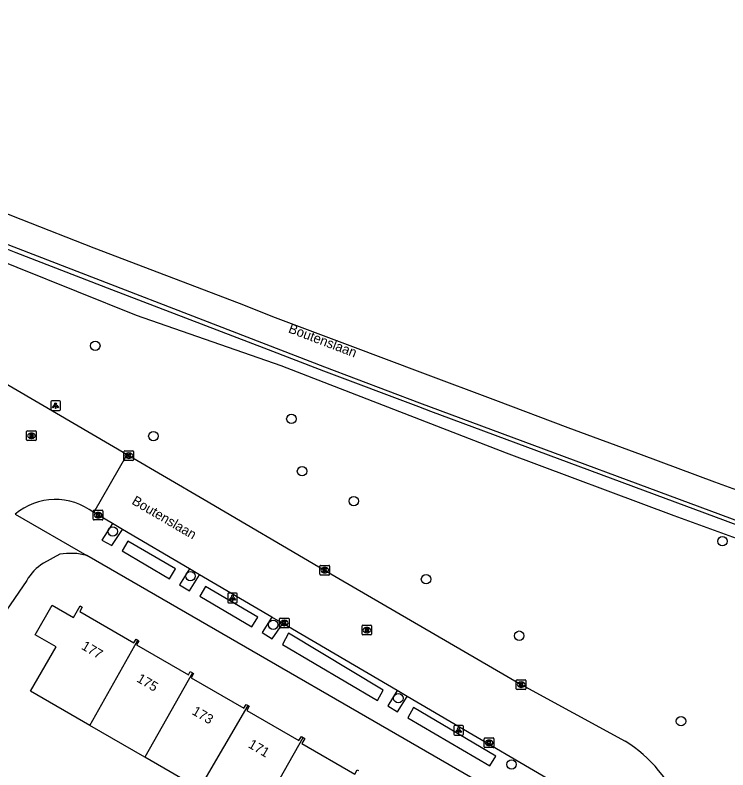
# Model space of a CAD drawing. Extents: x 160158 to 160921, y 381517 to 382041.
# Drawn here: x 160717.9 to 160791.9, y 381808.9 to 381887.3 of the extents above; entities that cross this region are included whole.
import ezdxf

# ---------------------------------------------------------------- set-up
doc = ezdxf.new("R2010")
doc.units = 0
for name, color, linetype in [('IMGEO_Boom', 7, 'Continuous'), ('IMGEO_Haag', 7, 'Continuous'), ('IMGEO_Kolk', 7, 'Continuous'), ('IMGEO_Lichtpunt', 7, 'Continuous'), ('IMGEO_Openbare_ruimte_label', 7, 'Continuous'), ('IMGEO_Pand', 7, 'Continuous'), ('IMGEO_Pand_nummerreeks', 7, 'Continuous'), ('IMGEO_Rijbaan_lokaal_open', 7, 'Continuous'), ('IMGEO_Rijbaan_regionaal_gesloten', 7, 'Continuous'), ('IMGEO_Rioolput', 7, 'Continuous'), ('IMGEO_Voetpad_open', 7, 'Continuous')]:
    doc.layers.add(name, color=color, linetype=linetype)

msp = doc.modelspace()

# ---------------------------------------------------------------- linework, layer by layer
at = {"layer": 'IMGEO_Boom'}
for centre in [(160726.203, 381852.954), (160746.556, 381845.36), (160732.229, 381843.573), (160747.662, 381839.926), (160753.032, 381836.818), (160728.01, 381833.663), (160791.302, 381832.657), (160736.072, 381829.024), (160760.535, 381828.709), (160744.672, 381823.974), (160770.206, 381822.841), (160757.66, 381816.345), (160787.002, 381813.963), (160769.415, 381809.472)]:
    msp.add_circle(centre, 0.489, dxfattribs=at)
at = {"layer": 'IMGEO_Haag'}
msp.add_lwpolyline([(160745.511, 381850.872), (160730.476, 381856.085), (160711.881, 381863.555), (160711.475, 381863.718), (160712.09, 381864.933), (160713.245, 381864.496), (160717.081, 381862.972), (160717.946, 381862.628), (160727.896, 381858.807), (160743.715, 381852.731), (160749.887, 381850.361), (160759.752, 381846.628), (160760.992, 381846.167), (160784.208, 381837.543), (160791.578, 381834.806), (160797.451, 381832.626), (160796.951, 381831.418), (160786.29, 381835.29), (160768.888, 381841.8), (160745.511, 381850.872)], dxfattribs=at)
at = {"layer": 'IMGEO_Kolk'}
for p, q in [((160729.183, 381841.112), (160729.183, 381841.964)), ((160729.258, 381842.038), (160730.11, 381842.038)), ((160729.671, 381841.818), (160729.696, 381841.818)), ((160730.184, 381841.964), (160730.184, 381841.112)), ((160730.11, 381841.038), (160729.258, 381841.038)), ((160729.694, 381841.258), (160729.669, 381841.258)), ((160725.997, 381834.935), (160725.997, 381835.787)), ((160726.072, 381835.861), (160726.924, 381835.861)), ((160726.485, 381835.641), (160726.51, 381835.641)), ((160726.998, 381835.787), (160726.998, 381834.935)), ((160726.924, 381834.861), (160726.072, 381834.861)), ((160726.508, 381835.081), (160726.483, 381835.081)), ((160749.521, 381829.216), (160749.521, 381830.068)), ((160749.596, 381830.142), (160750.448, 381830.142)), ((160750.009, 381829.922), (160750.034, 381829.922)), ((160750.522, 381830.068), (160750.522, 381829.216)), ((160750.448, 381829.142), (160749.596, 381829.142)), ((160750.032, 381829.362), (160750.007, 381829.362)), ((160745.316, 381823.737), (160745.316, 381824.589)), ((160745.391, 381824.663), (160746.243, 381824.663)), ((160745.804, 381824.443), (160745.829, 381824.443)), ((160746.317, 381824.589), (160746.317, 381823.737)), ((160746.243, 381823.663), (160745.391, 381823.663)), ((160745.827, 381823.883), (160745.802, 381823.883)), ((160769.907, 381817.333), (160769.907, 381818.185)), ((160769.982, 381818.259), (160770.834, 381818.259)), ((160770.395, 381818.039), (160770.42, 381818.039)), ((160770.908, 381818.185), (160770.908, 381817.333)), ((160770.834, 381817.259), (160769.982, 381817.259)), ((160770.418, 381817.479), (160770.393, 381817.479)), ((160766.579, 381811.296), (160766.579, 381812.148)), ((160766.654, 381812.222), (160767.506, 381812.222)), ((160767.067, 381812.002), (160767.092, 381812.002)), ((160767.58, 381812.148), (160767.58, 381811.296)), ((160767.506, 381811.222), (160766.654, 381811.222)), ((160767.09, 381811.442), (160767.065, 381811.442))]:
    msp.add_line(p, q, dxfattribs=at)
for points in [[(160729.183, 381841.112), (160729.183, 381841.964)], [(160729.258, 381842.038), (160730.11, 381842.038)], [(160729.504, 381841.738), (160729.627, 381841.738), (160729.627, 381841.587), (160729.757, 381841.738), (160729.921, 381841.738), (160729.775, 381841.587), (160729.928, 381841.338), (160729.776, 381841.338), (160729.691, 381841.502), (160729.627, 381841.435), (160729.627, 381841.338), (160729.504, 381841.338), (160729.504, 381841.738)], [(160730.184, 381841.964), (160730.184, 381841.112)], [(160730.11, 381841.038), (160729.258, 381841.038)], [(160725.997, 381834.935), (160725.997, 381835.787)], [(160726.072, 381835.861), (160726.924, 381835.861)], [(160726.318, 381835.561), (160726.441, 381835.561), (160726.441, 381835.41), (160726.571, 381835.561), (160726.735, 381835.561), (160726.589, 381835.41), (160726.742, 381835.161), (160726.59, 381835.161), (160726.505, 381835.325), (160726.441, 381835.258), (160726.441, 381835.161), (160726.318, 381835.161), (160726.318, 381835.561)], [(160726.998, 381835.787), (160726.998, 381834.935)], [(160726.924, 381834.861), (160726.072, 381834.861)], [(160749.521, 381829.216), (160749.521, 381830.068)], [(160749.596, 381830.142), (160750.448, 381830.142)], [(160749.842, 381829.842), (160749.965, 381829.842), (160749.965, 381829.691), (160750.095, 381829.842), (160750.259, 381829.842), (160750.113, 381829.691), (160750.266, 381829.442), (160750.114, 381829.442), (160750.029, 381829.606), (160749.965, 381829.539), (160749.965, 381829.442), (160749.842, 381829.442), (160749.842, 381829.842)], [(160750.522, 381830.068), (160750.522, 381829.216)], [(160750.448, 381829.142), (160749.596, 381829.142)], [(160745.316, 381823.737), (160745.316, 381824.589)], [(160745.391, 381824.663), (160746.243, 381824.663)], [(160745.637, 381824.363), (160745.76, 381824.363), (160745.76, 381824.212), (160745.89, 381824.363), (160746.054, 381824.363), (160745.908, 381824.212), (160746.061, 381823.963), (160745.909, 381823.963), (160745.824, 381824.127), (160745.76, 381824.06), (160745.76, 381823.963), (160745.637, 381823.963), (160745.637, 381824.363)], [(160746.317, 381824.589), (160746.317, 381823.737)], [(160746.243, 381823.663), (160745.391, 381823.663)], [(160769.907, 381817.333), (160769.907, 381818.185)], [(160769.982, 381818.259), (160770.834, 381818.259)], [(160770.908, 381818.185), (160770.908, 381817.333)], [(160770.834, 381817.259), (160769.982, 381817.259)], [(160770.228, 381817.959), (160770.351, 381817.959), (160770.351, 381817.808), (160770.481, 381817.959), (160770.645, 381817.959), (160770.499, 381817.808), (160770.652, 381817.559), (160770.5, 381817.559), (160770.415, 381817.723), (160770.351, 381817.656), (160770.351, 381817.559), (160770.228, 381817.559), (160770.228, 381817.959)], [(160766.579, 381811.296), (160766.579, 381812.148)], [(160766.654, 381812.222), (160767.506, 381812.222)], [(160766.9, 381811.922), (160767.023, 381811.922), (160767.023, 381811.771), (160767.153, 381811.922), (160767.317, 381811.922), (160767.171, 381811.771), (160767.324, 381811.522), (160767.172, 381811.522), (160767.087, 381811.686), (160767.023, 381811.619), (160767.023, 381811.522), (160766.9, 381811.522), (160766.9, 381811.922)], [(160767.58, 381812.148), (160767.58, 381811.296)], [(160767.506, 381811.222), (160766.654, 381811.222)]]:
    msp.add_lwpolyline(points, dxfattribs=at)
for centre, start, end in [((160729.26, 381841.962), 91.55205, 178.44795), ((160729.26, 381841.962), 91.55205, 178.44795), ((160730.108, 381841.962), 1.55205, 88.44795), ((160730.108, 381841.962), 1.55205, 88.44795), ((160729.26, 381841.114), 181.55205, 268.44795), ((160729.26, 381841.114), 181.55205, 268.44795), ((160730.108, 381841.114), 271.55205, 358.44795), ((160730.108, 381841.114), 271.55205, 358.44795), ((160726.074, 381835.785), 91.55205, 178.44795), ((160726.074, 381835.785), 91.55205, 178.44795), ((160726.922, 381835.785), 1.55205, 88.44795), ((160726.922, 381835.785), 1.55205, 88.44795), ((160726.074, 381834.937), 181.55205, 268.44795), ((160726.074, 381834.937), 181.55205, 268.44795), ((160726.922, 381834.937), 271.55205, 358.44795), ((160726.922, 381834.937), 271.55205, 358.44795), ((160749.598, 381830.066), 91.55205, 178.44795), ((160749.598, 381830.066), 91.55205, 178.44795), ((160750.446, 381830.066), 1.55205, 88.44795), ((160750.446, 381830.066), 1.55205, 88.44795), ((160749.598, 381829.218), 181.55205, 268.44795), ((160749.598, 381829.218), 181.55205, 268.44795), ((160750.446, 381829.218), 271.55205, 358.44795), ((160750.446, 381829.218), 271.55205, 358.44795), ((160745.393, 381824.587), 91.55205, 178.44795), ((160745.393, 381824.587), 91.55205, 178.44795), ((160746.241, 381824.587), 1.55205, 88.44795), ((160746.241, 381824.587), 1.55205, 88.44795), ((160745.393, 381823.739), 181.55205, 268.44795), ((160745.393, 381823.739), 181.55205, 268.44795), ((160746.241, 381823.739), 271.55205, 358.44795), ((160746.241, 381823.739), 271.55205, 358.44795), ((160769.984, 381818.183), 91.55205, 178.44795), ((160769.984, 381818.183), 91.55205, 178.44795), ((160770.832, 381818.183), 1.55205, 88.44795), ((160770.832, 381818.183), 1.55205, 88.44795), ((160769.984, 381817.335), 181.55205, 268.44795), ((160769.984, 381817.335), 181.55205, 268.44795), ((160770.832, 381817.335), 271.55205, 358.44795), ((160770.832, 381817.335), 271.55205, 358.44795), ((160766.656, 381812.146), 91.55205, 178.44795), ((160766.656, 381812.146), 91.55205, 178.44795), ((160767.504, 381812.146), 1.55205, 88.44795), ((160767.504, 381812.146), 1.55205, 88.44795), ((160766.656, 381811.298), 181.55205, 268.44795), ((160766.656, 381811.298), 181.55205, 268.44795), ((160767.504, 381811.298), 271.55205, 358.44795), ((160767.504, 381811.298), 271.55205, 358.44795)]:
    msp.add_arc(centre, 0.0765, start, end, dxfattribs=at)
for centre, major_axis, ratio, start_param, end_param in [((160729.67, 381841.538), (-0.387, 0.002), 0.722429, 4.712389, 7.853982), ((160729.695, 381841.538), (-0.39, 0.002), 0.717154, 1.570796, 4.712389), ((160726.484, 381835.361), (-0.387, 0.002), 0.722429, 4.712389, 7.853982), ((160726.509, 381835.361), (-0.39, 0.002), 0.717154, 1.570796, 4.712389), ((160750.008, 381829.642), (-0.387, 0.002), 0.722429, 4.712389, 7.853982), ((160750.033, 381829.642), (-0.39, 0.002), 0.717154, 1.570796, 4.712389), ((160745.803, 381824.163), (-0.387, 0.002), 0.722429, 4.712389, 7.853982), ((160745.828, 381824.163), (-0.39, 0.002), 0.717154, 1.570796, 4.712389), ((160770.394, 381817.759), (-0.387, 0.002), 0.722429, 4.712389, 7.853982), ((160770.419, 381817.759), (-0.39, 0.002), 0.717154, 1.570796, 4.712389), ((160767.066, 381811.722), (-0.387, 0.002), 0.722429, 4.712389, 7.853982), ((160767.091, 381811.722), (-0.39, 0.002), 0.717154, 1.570796, 4.712389)]:
    msp.add_ellipse(centre, major_axis=major_axis, ratio=ratio, start_param=start_param, end_param=end_param, dxfattribs=at)
at = {"layer": 'IMGEO_Lichtpunt'}
for p, q in [((160721.587, 381847.135), (160721.587, 381846.328)), ((160721.587, 381847.135), (160721.587, 381846.328)), ((160722.489, 381847.23), (160721.681, 381847.23)), ((160722.489, 381847.23), (160721.681, 381847.23)), ((160722.583, 381846.328), (160722.583, 381847.135)), ((160722.583, 381846.328), (160722.583, 381847.135)), ((160721.681, 381846.234), (160722.489, 381846.234)), ((160721.681, 381846.234), (160722.489, 381846.234)), ((160739.946, 381827.149), (160739.946, 381826.342)), ((160739.946, 381827.149), (160739.946, 381826.342)), ((160740.848, 381827.244), (160740.04, 381827.244)), ((160740.848, 381827.244), (160740.04, 381827.244)), ((160740.942, 381826.342), (160740.942, 381827.149)), ((160740.942, 381826.342), (160740.942, 381827.149)), ((160740.04, 381826.248), (160740.848, 381826.248)), ((160740.04, 381826.248), (160740.848, 381826.248)), ((160763.418, 381813.41), (160763.418, 381812.603)), ((160763.418, 381813.41), (160763.418, 381812.603)), ((160764.32, 381813.505), (160763.512, 381813.505)), ((160764.32, 381813.505), (160763.512, 381813.505)), ((160764.414, 381812.603), (160764.414, 381813.41)), ((160764.414, 381812.603), (160764.414, 381813.41)), ((160763.512, 381812.509), (160764.32, 381812.509)), ((160763.512, 381812.509), (160764.32, 381812.509))]:
    msp.add_line(p, q, dxfattribs=at)
for points in [[(160721.961, 381846.799), (160722, 381846.771), (160721.812, 381846.509), (160721.774, 381846.536), (160721.961, 381846.799)], [(160722.063, 381846.751), (160722.11, 381846.751), (160722.11, 381846.429), (160722.063, 381846.429), (160722.063, 381846.751)], [(160722.173, 381846.771), (160722.211, 381846.798), (160722.398, 381846.536), (160722.359, 381846.508), (160722.173, 381846.771)], [(160740.32, 381826.813), (160740.359, 381826.785), (160740.171, 381826.523), (160740.133, 381826.55), (160740.32, 381826.813)], [(160740.422, 381826.765), (160740.469, 381826.765), (160740.469, 381826.443), (160740.422, 381826.443), (160740.422, 381826.765)], [(160740.532, 381826.785), (160740.57, 381826.812), (160740.757, 381826.55), (160740.718, 381826.522), (160740.532, 381826.785)], [(160763.792, 381813.074), (160763.831, 381813.046), (160763.643, 381812.784), (160763.605, 381812.811), (160763.792, 381813.074)], [(160763.894, 381813.026), (160763.941, 381813.026), (160763.941, 381812.704), (160763.894, 381812.704), (160763.894, 381813.026)], [(160764.004, 381813.046), (160764.042, 381813.073), (160764.229, 381812.811), (160764.19, 381812.783), (160764.004, 381813.046)]]:
    msp.add_lwpolyline(points, dxfattribs=at)
for centre in [(160722.086, 381846.933), (160740.445, 381826.947), (160763.917, 381813.208)]:
    msp.add_circle(centre, 0.0994, dxfattribs=at)
for centre, start, end in [((160721.681, 381847.135), 90, 180), ((160721.681, 381847.135), 90, 180), ((160722.489, 381847.135), 0, 90), ((160722.489, 381847.135), 0, 90), ((160721.681, 381846.328), 180, 270), ((160721.681, 381846.328), 180, 270), ((160722.489, 381846.328), 270, 0), ((160722.489, 381846.328), 270, 360), ((160740.04, 381827.149), 90, 180), ((160740.04, 381827.149), 90, 180), ((160740.848, 381827.149), 0, 90), ((160740.848, 381827.149), 0, 90), ((160740.04, 381826.342), 180, 270), ((160740.04, 381826.342), 180, 270), ((160740.848, 381826.342), 270, 0), ((160740.848, 381826.342), 270, 360), ((160763.512, 381813.41), 90, 180), ((160763.512, 381813.41), 90, 180), ((160764.32, 381813.41), 0, 90), ((160764.32, 381813.41), 0, 90), ((160763.512, 381812.603), 180, 270), ((160763.512, 381812.603), 180, 270), ((160764.32, 381812.603), 270, 0), ((160764.32, 381812.603), 270, 360)]:
    msp.add_arc(centre, 0.0946, start, end, dxfattribs=at)
at = {"layer": 'IMGEO_Pand'}
for points in [[(160725.622, 381813.528), (160719.482, 381817.076), (160722.136, 381821.67), (160719.958, 381822.928), (160721.739, 381826.011), (160723.944, 381824.737), (160724.631, 381825.926), (160724.835, 381825.808), (160724.582, 381825.37), (160730.22, 381822.112), (160730.435, 381822.484), (160730.625, 381822.374)], [(160725.622, 381813.528), (160730.625, 381822.374)], [(160730.625, 381822.374), (160730.713, 381822.323), (160730.466, 381821.896), (160735.865, 381818.776), (160736.063, 381819.12), (160736.28, 381818.995)], [(160736.28, 381818.995), (160731.333, 381810.229)], [(160736.28, 381818.995), (160736.405, 381818.922), (160736.147, 381818.475), (160741.637, 381815.302), (160741.874, 381815.712), (160742.071, 381815.598)], [(160737.027, 381806.939), (160742.071, 381815.598)], [(160742.071, 381815.598), (160742.181, 381815.535), (160741.919, 381815.081), (160747.348, 381811.944), (160747.592, 381812.367), (160747.786, 381812.255)], [(160731.333, 381810.229), (160725.622, 381813.528)], [(160742.859, 381803.57), (160747.786, 381812.255)], [(160747.786, 381812.255), (160747.954, 381812.158), (160747.652, 381811.636), (160753.139, 381808.466), (160753.396, 381808.91), (160753.538, 381808.828)], [(160737.027, 381806.939), (160731.333, 381810.229)]]:
    msp.add_lwpolyline(points, dxfattribs=at)
at = {"layer": 'IMGEO_Rijbaan_lokaal_open'}
for points in [[(160710.739, 381852.616), (160729.517, 381841.642)], [(160726.038, 381835.628), (160729.517, 381841.642)], [(160729.517, 381841.642), (160729.683, 381841.537), (160737.491, 381836.968), (160750, 381829.655), (160770.407, 381817.758), (160781.21, 381811.887)], [(160727.975, 381834.491), (160726.038, 381835.628)], [(160729.025, 381833.876), (160727.975, 381834.491)], [(160735.994, 381829.787), (160729.025, 381833.876)], [(160737.031, 381829.178), (160735.994, 381829.787)], [(160744.536, 381824.775), (160737.031, 381829.178)], [(160745.656, 381824.118), (160744.536, 381824.775)], [(160757.549, 381817.141), (160745.656, 381824.118)], [(160758.57, 381816.542), (160757.549, 381817.141)], [(160778.552, 381804.819), (160758.57, 381816.542)]]:
    msp.add_lwpolyline(points, dxfattribs=at)
for centre, radius, start, end in [((160722.068, 381830.498), 6.486, 52.2665, 130.23307), ((160773.302, 381799.362), 14.812, 21.87474, 57.73319)]:
    msp.add_arc(centre, radius, start, end, dxfattribs=at)
at = {"layer": 'IMGEO_Rijbaan_regionaal_gesloten'}
for points in [[(160666.412, 381887.287), (160673.473, 381884.284), (160681.081, 381881.148), (160688.421, 381878.123), (160695.846, 381875.139), (160703.27, 381872.155), (160710.78, 381869.136), (160718.463, 381866.1), (160726.041, 381863.104), (160733.591, 381860.234), (160741.14, 381857.364), (160744.861, 381855.899), (160752.618, 381852.985), (160760.179, 381850.143), (160767.74, 381847.302), (160775.267, 381844.473), (160782.85, 381841.672), (160790.477, 381838.833), (160798.092, 381836.06)], [(160797.563, 381833.009), (160759.891, 381847.003), (160750.031, 381850.734), (160713.638, 381864.767), (160713.148, 381864.956)]]:
    msp.add_lwpolyline(points, dxfattribs=at)
at = {"layer": 'IMGEO_Rioolput'}
for p, q in [((160719.075, 381843.184), (160719.075, 381844.036)), ((160719.15, 381844.11), (160720.002, 381844.11)), ((160719.563, 381843.89), (160719.588, 381843.89)), ((160720.076, 381844.036), (160720.076, 381843.184)), ((160720.002, 381843.11), (160719.15, 381843.11)), ((160719.586, 381843.33), (160719.561, 381843.33)), ((160753.889, 381823.001), (160753.889, 381823.853)), ((160753.964, 381823.927), (160754.816, 381823.927)), ((160754.377, 381823.707), (160754.402, 381823.707)), ((160754.89, 381823.853), (160754.89, 381823.001)), ((160754.816, 381822.927), (160753.964, 381822.927)), ((160754.4, 381823.147), (160754.375, 381823.147))]:
    msp.add_line(p, q, dxfattribs=at)
for points in [[(160719.075, 381843.184), (160719.075, 381844.036)], [(160719.15, 381844.11), (160720.002, 381844.11)], [(160720.076, 381844.036), (160720.076, 381843.184)], [(160720.002, 381843.11), (160719.15, 381843.11)], [(160719.664, 381843.808), (160719.412, 381843.81), (160719.412, 381843.41)], [(160719.412, 381843.41), (160719.536, 381843.41), (160719.536, 381843.572), (160719.547, 381843.572)], [(160719.59, 381843.729), (160719.536, 381843.729), (160719.536, 381843.648)], [(160719.536, 381843.648), (160719.588, 381843.648)], [(160719.594, 381843.543), (160719.665, 381843.41), (160719.805, 381843.41), (160719.74, 381843.536)], [(160753.889, 381823.001), (160753.889, 381823.853)], [(160753.964, 381823.927), (160754.816, 381823.927)], [(160754.478, 381823.625), (160754.226, 381823.627), (160754.226, 381823.227)], [(160754.404, 381823.546), (160754.35, 381823.546), (160754.35, 381823.465)], [(160754.89, 381823.853), (160754.89, 381823.001)], [(160754.816, 381822.927), (160753.964, 381822.927)], [(160754.226, 381823.227), (160754.35, 381823.227), (160754.35, 381823.389), (160754.361, 381823.389)], [(160754.35, 381823.465), (160754.402, 381823.465)], [(160754.408, 381823.36), (160754.479, 381823.227), (160754.619, 381823.227), (160754.554, 381823.353)]]:
    msp.add_lwpolyline(points, dxfattribs=at)
for centre, radius, start, end in [((160719.152, 381844.034), 0.0765, 91.55205, 178.44795), ((160719.152, 381844.034), 0.0765, 91.55205, 178.44795), ((160720, 381844.034), 0.0765, 1.55205, 88.44795), ((160720, 381844.034), 0.0765, 1.55205, 88.44795), ((160719.152, 381843.186), 0.0765, 181.55205, 268.44795), ((160719.152, 381843.186), 0.0765, 181.55205, 268.44795), ((160719.546, 381843.519), 0.0533, 26.02933, 88.69889), ((160719.572, 381843.837), 0.19, 274.7715, 282.96867), ((160719.596, 381843.633), 0.0964, 77.00612, 93.18647), ((160719.61, 381843.69), 0.0378, 276.66336, 79.67722), ((160719.663, 381843.698), 0.109, 350.36119, 89.41601), ((160719.661, 381843.698), 0.112, 277.58423, 350.98172), ((160719.645, 381843.483), 0.108, 29.51342, 73.79051), ((160720, 381843.186), 0.0765, 271.55205, 358.44795), ((160720, 381843.186), 0.0765, 271.55205, 358.44795), ((160753.966, 381823.851), 0.0765, 91.55205, 178.44795), ((160753.966, 381823.851), 0.0765, 91.55205, 178.44795), ((160754.41, 381823.45), 0.0964, 77.00612, 93.18647), ((160754.424, 381823.507), 0.0378, 276.66336, 79.67722), ((160754.477, 381823.515), 0.109, 350.36119, 89.41601), ((160754.475, 381823.515), 0.112, 277.58423, 350.98172), ((160754.814, 381823.851), 0.0765, 1.55205, 88.44795), ((160754.814, 381823.851), 0.0765, 1.55205, 88.44795), ((160753.966, 381823.003), 0.0765, 181.55205, 268.44795), ((160753.966, 381823.003), 0.0765, 181.55205, 268.44795), ((160754.36, 381823.336), 0.0533, 26.02933, 88.69889), ((160754.386, 381823.654), 0.19, 274.7715, 282.96867), ((160754.459, 381823.3), 0.108, 29.51342, 73.79051), ((160754.814, 381823.003), 0.0765, 271.55205, 358.44795), ((160754.814, 381823.003), 0.0765, 271.55205, 358.44795)]:
    msp.add_arc(centre, radius, start, end, dxfattribs=at)
for centre, major_axis, ratio, start_param, end_param in [((160719.562, 381843.61), (-0.387, 0.002), 0.722429, 4.712389, 7.853982), ((160719.587, 381843.61), (-0.39, 0.002), 0.717154, 1.570796, 4.712389), ((160754.376, 381823.427), (-0.387, 0.002), 0.722429, 4.712389, 7.853982), ((160754.401, 381823.427), (-0.39, 0.002), 0.717154, 1.570796, 4.712389)]:
    msp.add_ellipse(centre, major_axis=major_axis, ratio=ratio, start_param=start_param, end_param=end_param, dxfattribs=at)
at = {"layer": 'IMGEO_Voetpad_open'}
for points in [[(160717.879, 381835.45), (160725.308, 381831.17)], [(160727.975, 381834.491), (160726.88, 381832.779), (160727.916, 381832.202), (160729.025, 381833.876)], [(160734.514, 381829.772), (160729.598, 381832.666), (160728.98, 381831.646), (160733.89, 381828.734), (160734.514, 381829.772)], [(160722.519, 381831.291), (160720.826, 381830.369)], [(160772.287, 381804.027), (160725.308, 381831.17)], [(160735.994, 381829.787), (160734.958, 381828.113), (160735.975, 381827.493), (160737.031, 381829.178)], [(160719.08, 381828.577), (160705.185, 381808.313)], [(160743.086, 381824.778), (160737.651, 381827.941), (160737.059, 381826.933), (160742.461, 381823.753), (160743.086, 381824.778)], [(160744.536, 381824.775), (160743.527, 381823.172), (160744.575, 381822.512), (160745.656, 381824.118)], [(160756.101, 381817.186), (160746.269, 381823.113), (160745.637, 381821.942), (160755.507, 381816.114), (160756.101, 381817.186)], [(160757.549, 381817.141), (160756.566, 381815.554), (160757.583, 381814.944), (160758.57, 381816.542)], [(160767.78, 381810.342), (160759.236, 381815.369), (160758.641, 381814.314), (160767.167, 381809.343), (160767.78, 381810.342)]]:
    msp.add_lwpolyline(points, dxfattribs=at)
for centre, radius, start, end in [((160723.647, 381825.095), 6.298, 74.71018, 100.32141), ((160723.418, 381826.097), 4.997, 121.24772, 150.24208)]:
    msp.add_arc(centre, radius, start, end, dxfattribs=at)

# ---------------------------------------------------------------- texts
at = {"layer": 'IMGEO_Openbare_ruimte_label'}
for rotation, p in [(339.26285, (160746.168, 381854.354)), (329.61576, (160729.912, 381836.571))]:
    msp.add_text('Boutenslaan', height=1, rotation=rotation, dxfattribs=at).set_placement(p)
at = {"layer": 'IMGEO_Pand_nummerreeks'}
for s, p in [('177', (160724.677, 381821.506)), ('175', (160730.416, 381818.122)), ('173', (160736.155, 381814.738)), ('171', (160741.991, 381811.295))]:
    msp.add_text(s, height=1, rotation=329.47198, dxfattribs=at).set_placement(p)

doc.saveas('drawing.dxf')
